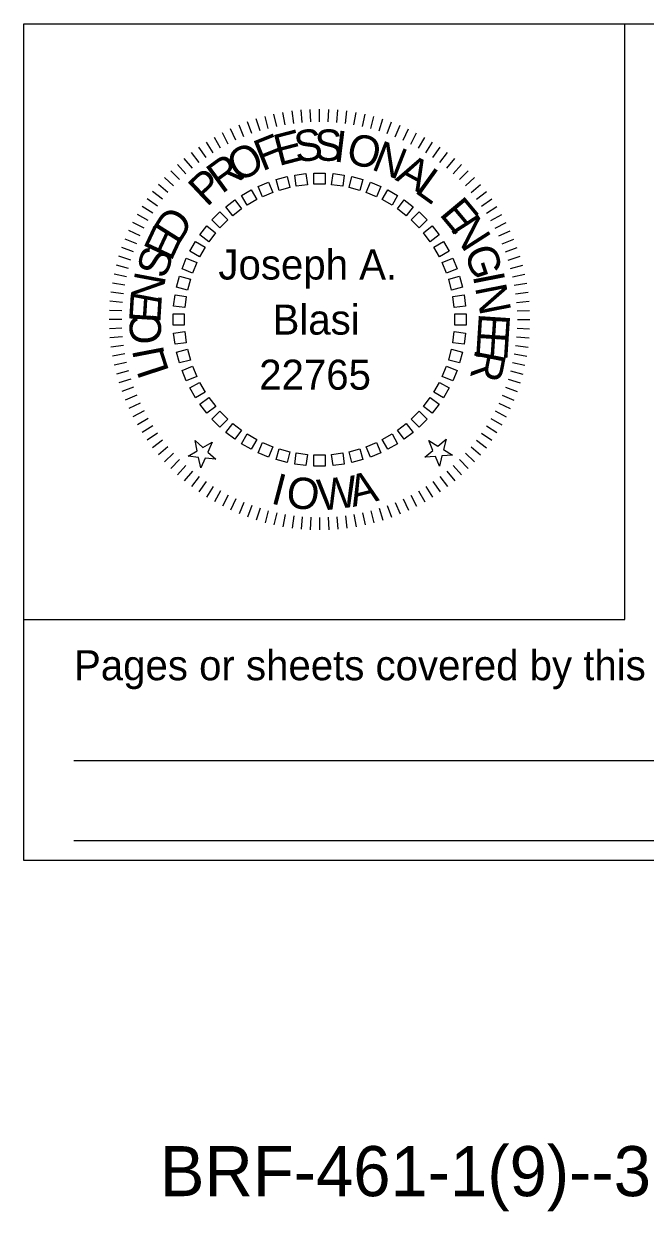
# Model space of a CAD drawing. Extents: x 10040 to 81668, y 7194 to 11018.
# Drawn here: x 12188.1 to 12436.3, y 7193.8 to 7667.9 of the extents above; entities that cross this region are included whole.
import ezdxf

# ---------------------------------------------------------------- set-up
doc = ezdxf.new("R2010")
doc.units = 0
doc.layers.add('dsnCellsSignature', color=7, linetype='Continuous')
doc.layers.add('dsnTextCpn', color=7, linetype='Continuous')

msp = doc.modelspace()

# ---------------------------------------------------------------- linework, layer by layer
at = {"layer": 'dsnCellsSignature'}
for p, q in [((12428.13, 7430.03), (12428.13, 7667.92)), ((12188.13, 7430.03), (12428.13, 7430.03)), ((12208.2, 7373.8), (12918.13, 7373.8)), ((12208.2, 7341.8), (12918.13, 7341.8))]:
    msp.add_line(p, q, dxfattribs=at)
msp.add_lwpolyline([(12188.13, 7667.92), (12938.13, 7667.92), (12938.13, 7333.8), (12188.13, 7333.8)], close=True, dxfattribs=at)
at = {"layer": 'dsnTextCpn'}
for p, q in [((12299.37, 7628.51), (12298.93, 7633.49)), ((12302.8, 7628.73), (12302.58, 7633.73)), ((12306.25, 7628.81), (12306.25, 7633.81)), ((12306.25, 7628.81), (12306.25, 7633.81)), ((12309.7, 7628.73), (12309.91, 7633.73)), ((12313.13, 7628.51), (12313.57, 7633.49)), ((12279.23, 7624.04), (12277.52, 7628.74)), ((12282.49, 7625.15), (12280.99, 7629.92)), ((12285.8, 7626.11), (12284.51, 7630.95)), ((12289.15, 7626.93), (12288.07, 7631.82)), ((12292.53, 7627.61), (12291.66, 7632.53)), ((12295.94, 7628.13), (12295.28, 7633.09)), ((12316.56, 7628.13), (12317.21, 7633.09)), ((12319.97, 7627.61), (12320.84, 7632.53)), ((12323.35, 7626.93), (12324.43, 7631.82)), ((12326.7, 7626.11), (12327.99, 7630.94)), ((12330.01, 7625.15), (12331.51, 7629.92)), ((12333.27, 7624.04), (12334.98, 7628.74)), ((12269.77, 7619.88), (12267.46, 7624.32)), ((12272.86, 7621.4), (12270.75, 7625.94)), ((12276.02, 7622.79), (12274.1, 7627.41)), ((12336.48, 7622.79), (12338.4, 7627.41)), ((12339.64, 7621.4), (12341.75, 7625.94)), ((12342.73, 7619.88), (12345.04, 7624.32)), ((12263.8, 7616.44), (12261.12, 7620.65)), ((12266.75, 7618.22), (12264.25, 7622.55)), ((12345.75, 7618.22), (12348.25, 7622.55)), ((12348.7, 7616.44), (12351.38, 7620.65)), ((12258.15, 7612.48), (12255.11, 7616.45)), ((12260.94, 7614.52), (12258.07, 7618.62)), ((12351.56, 7614.52), (12354.43, 7618.61)), ((12354.34, 7612.48), (12357.39, 7616.45)), ((12252.88, 7608.05), (12249.5, 7611.74)), ((12255.47, 7610.32), (12252.25, 7614.15)), ((12357.03, 7610.32), (12360.25, 7614.15)), ((12359.62, 7608.05), (12363, 7611.74)), ((12248, 7603.18), (12244.32, 7606.56)), ((12250.39, 7605.67), (12246.85, 7609.2)), ((12362.11, 7605.67), (12365.65, 7609.2)), ((12364.5, 7603.18), (12368.18, 7606.56)), ((12243.57, 7597.9), (12239.6, 7600.94)), ((12245.73, 7600.59), (12241.9, 7603.8)), ((12366.77, 7600.59), (12370.6, 7603.8)), ((12368.93, 7597.9), (12372.89, 7600.94)), ((12241.53, 7595.12), (12237.44, 7597.99)), ((12370.97, 7595.12), (12375.06, 7597.99)), ((12237.83, 7589.31), (12233.5, 7591.81)), ((12239.62, 7592.25), (12235.4, 7594.94)), ((12372.88, 7592.25), (12377.1, 7594.94)), ((12374.67, 7589.3), (12379, 7591.8)), ((12236.17, 7586.28), (12231.74, 7588.59)), ((12376.33, 7586.28), (12380.76, 7588.59)), ((12233.26, 7580.04), (12228.64, 7581.95)), ((12234.65, 7583.19), (12230.12, 7585.31)), ((12377.85, 7583.19), (12382.38, 7585.3)), ((12379.24, 7580.04), (12383.86, 7581.95)), ((12232.01, 7576.82), (12227.31, 7578.53)), ((12380.49, 7576.82), (12385.19, 7578.53)), ((12230.9, 7573.56), (12226.13, 7575.06)), ((12381.6, 7573.56), (12386.37, 7575.06)), ((12229.12, 7566.9), (12224.24, 7567.99)), ((12229.94, 7570.25), (12225.11, 7571.55)), ((12382.56, 7570.25), (12387.39, 7571.55)), ((12383.38, 7566.9), (12388.26, 7567.98)), ((12228.45, 7563.52), (12223.52, 7564.39)), ((12384.05, 7563.52), (12388.98, 7564.39)), ((12227.92, 7560.11), (12222.96, 7560.77)), ((12384.58, 7560.11), (12389.53, 7560.77)), ((12227.32, 7553.25), (12222.33, 7553.47)), ((12227.55, 7556.69), (12222.57, 7557.12)), ((12384.95, 7556.69), (12389.93, 7557.12)), ((12385.18, 7553.25), (12390.17, 7553.46)), ((12227.24, 7549.8), (12222.24, 7549.8)), ((12385.25, 7549.8), (12390.25, 7549.8)), ((12227.32, 7546.36), (12222.33, 7546.14)), ((12385.18, 7546.36), (12390.17, 7546.14)), ((12227.55, 7542.92), (12222.57, 7542.48)), ((12227.92, 7539.49), (12222.96, 7538.84)), ((12384.58, 7539.49), (12389.53, 7538.84)), ((12384.95, 7542.92), (12389.93, 7542.48)), ((12228.45, 7536.08), (12223.52, 7535.22)), ((12384.05, 7536.08), (12388.98, 7535.21)), ((12229.12, 7532.7), (12224.24, 7531.62)), ((12229.94, 7529.36), (12225.11, 7528.06)), ((12382.56, 7529.36), (12387.39, 7528.06)), ((12383.38, 7532.7), (12388.26, 7531.62)), ((12230.9, 7526.05), (12226.13, 7524.54)), ((12381.6, 7526.05), (12386.36, 7524.54)), ((12232.01, 7522.78), (12227.31, 7521.07)), ((12380.49, 7522.78), (12385.19, 7521.07)), ((12233.26, 7519.57), (12228.64, 7517.66)), ((12234.65, 7516.42), (12230.12, 7514.3)), ((12377.85, 7516.41), (12382.38, 7514.3)), ((12379.24, 7519.57), (12383.86, 7517.65)), ((12236.17, 7513.32), (12231.74, 7511.01)), ((12237.83, 7510.3), (12233.5, 7507.8)), ((12374.67, 7510.3), (12379, 7507.8)), ((12376.33, 7513.32), (12380.76, 7511.01)), ((12239.62, 7507.36), (12235.4, 7504.67)), ((12372.88, 7507.36), (12377.1, 7504.67)), ((12241.53, 7504.49), (12237.44, 7501.62)), ((12243.57, 7501.71), (12239.6, 7498.66)), ((12368.93, 7501.71), (12372.89, 7498.66)), ((12370.97, 7504.49), (12375.06, 7501.62)), ((12245.73, 7499.02), (12241.9, 7495.81)), ((12248, 7496.43), (12244.31, 7493.05)), ((12364.5, 7496.43), (12368.18, 7493.05)), ((12366.77, 7499.02), (12370.6, 7495.81)), ((12250.38, 7493.94), (12246.85, 7490.4)), ((12252.87, 7491.56), (12249.5, 7487.87)), ((12359.62, 7491.56), (12363, 7487.87)), ((12362.11, 7493.94), (12365.65, 7490.4)), ((12255.47, 7489.28), (12252.25, 7485.45)), ((12258.15, 7487.12), (12255.11, 7483.16)), ((12354.34, 7487.12), (12357.39, 7483.16)), ((12357.03, 7489.28), (12360.25, 7485.45)), ((12260.93, 7485.09), (12258.07, 7480.99)), ((12263.8, 7483.17), (12261.12, 7478.96)), ((12348.7, 7483.17), (12351.38, 7478.95)), ((12351.56, 7485.09), (12354.43, 7480.99)), ((12266.75, 7481.38), (12264.25, 7477.05)), ((12269.77, 7479.72), (12267.46, 7475.29)), ((12272.86, 7478.2), (12270.75, 7473.67)), ((12339.64, 7478.2), (12341.75, 7473.67)), ((12342.73, 7479.72), (12345.04, 7475.29)), ((12345.75, 7481.38), (12348.25, 7477.05)), ((12276.02, 7476.81), (12274.1, 7472.19)), ((12279.23, 7475.56), (12277.52, 7470.87)), ((12282.49, 7474.46), (12280.99, 7469.69)), ((12285.8, 7473.49), (12284.51, 7468.66)), ((12289.15, 7472.67), (12288.07, 7467.79)), ((12323.35, 7472.67), (12324.43, 7467.79)), ((12326.7, 7473.49), (12327.99, 7468.66)), ((12330.01, 7474.46), (12331.51, 7469.69)), ((12333.27, 7475.56), (12334.98, 7470.86)), ((12336.48, 7476.81), (12338.4, 7472.19)), ((12292.53, 7472), (12291.66, 7467.07)), ((12295.94, 7471.48), (12295.28, 7466.52)), ((12299.36, 7471.1), (12298.93, 7466.12)), ((12302.8, 7470.87), (12302.58, 7465.88)), ((12306.25, 7470.8), (12306.25, 7465.8)), ((12309.7, 7470.87), (12309.91, 7465.88)), ((12313.13, 7471.1), (12313.57, 7466.12)), ((12316.56, 7471.47), (12317.21, 7466.52)), ((12319.97, 7472), (12320.84, 7467.07))]:
    msp.add_line(p, q, dxfattribs=at)
for points in [[(12294.45, 7602.55), (12290.1, 7601.38), (12288.93, 7605.73), (12293.28, 7606.9)], [(12301.43, 7603.64), (12296.97, 7603.05), (12296.38, 7607.51), (12300.84, 7608.1)], [(12308.5, 7603.81), (12304, 7603.81), (12304, 7608.31), (12308.5, 7608.31)], [(12315.53, 7603.05), (12311.07, 7603.64), (12311.65, 7608.1), (12316.12, 7607.51)], [(12322.4, 7601.38), (12318.05, 7602.55), (12319.22, 7606.9), (12323.57, 7605.73)], [(12281.2, 7597.7), (12277.3, 7595.45), (12275.05, 7599.34), (12278.95, 7601.59)], [(12287.66, 7600.56), (12283.51, 7598.83), (12281.78, 7602.99), (12285.94, 7604.71)], [(12328.99, 7598.83), (12324.83, 7600.56), (12326.56, 7604.71), (12330.72, 7602.99)], [(12335.2, 7595.45), (12331.3, 7597.7), (12333.55, 7601.59), (12337.45, 7599.34)], [(12275.16, 7594.02), (12271.59, 7591.28), (12268.85, 7594.85), (12272.42, 7597.59)], [(12340.91, 7591.28), (12337.34, 7594.02), (12340.08, 7597.59), (12343.65, 7594.85)], [(12269.65, 7589.58), (12266.47, 7586.4), (12263.29, 7589.58), (12266.47, 7592.76)], [(12346.03, 7586.4), (12342.84, 7589.58), (12346.03, 7592.76), (12349.21, 7589.58)], [(12264.77, 7584.46), (12262.04, 7580.89), (12258.47, 7583.63), (12261.21, 7587.2)], [(12350.46, 7580.89), (12347.72, 7584.46), (12351.29, 7587.2), (12354.03, 7583.63)], [(12260.6, 7578.75), (12258.36, 7574.85), (12254.46, 7577.11), (12256.71, 7581)], [(12354.14, 7574.86), (12351.89, 7578.75), (12355.79, 7581), (12358.04, 7577.11)], [(12257.22, 7572.55), (12255.5, 7568.39), (12251.34, 7570.11), (12253.06, 7574.27)], [(12357, 7568.39), (12355.28, 7572.55), (12359.44, 7574.27), (12361.16, 7570.11)], [(12254.67, 7565.95), (12253.5, 7561.61), (12249.16, 7562.77), (12250.32, 7567.12)], [(12359, 7561.61), (12357.83, 7565.95), (12362.18, 7567.12), (12363.34, 7562.77)], [(12253, 7559.08), (12252.42, 7554.62), (12247.95, 7555.21), (12248.54, 7559.67)], [(12360.08, 7554.62), (12359.5, 7559.08), (12363.96, 7559.67), (12364.55, 7555.21)], [(12252.25, 7552.05), (12252.25, 7547.55), (12247.75, 7547.55), (12247.75, 7552.05)], [(12360.25, 7547.55), (12360.25, 7552.05), (12364.75, 7552.05), (12364.75, 7547.55)], [(12252.41, 7544.98), (12253, 7540.52), (12248.54, 7539.94), (12247.95, 7544.4)], [(12359.5, 7540.52), (12360.08, 7544.99), (12364.55, 7544.4), (12363.96, 7539.94)], [(12253.5, 7538), (12254.67, 7533.65), (12250.32, 7532.49), (12249.16, 7536.83)], [(12357.83, 7533.65), (12358.99, 7538), (12363.34, 7536.83), (12362.18, 7532.49)], [(12255.5, 7531.22), (12257.22, 7527.06), (12253.06, 7525.34), (12251.34, 7529.49)], [(12355.28, 7527.06), (12357, 7531.22), (12361.16, 7529.49), (12359.44, 7525.34)], [(12258.35, 7524.75), (12260.61, 7520.85), (12256.71, 7518.6), (12254.46, 7522.5)], [(12351.89, 7520.85), (12354.14, 7524.75), (12358.04, 7522.5), (12355.79, 7518.6)], [(12262.04, 7518.71), (12264.78, 7515.14), (12261.21, 7512.4), (12258.47, 7515.97)], [(12347.72, 7515.14), (12350.46, 7518.71), (12354.03, 7515.97), (12351.29, 7512.4)], [(12266.47, 7513.21), (12269.65, 7510.03), (12266.47, 7506.84), (12263.29, 7510.03)], [(12342.84, 7510.03), (12346.03, 7513.21), (12349.21, 7510.03), (12346.03, 7506.85)], [(12271.59, 7508.33), (12275.16, 7505.59), (12272.42, 7502.02), (12268.85, 7504.76)], [(12337.34, 7505.59), (12340.91, 7508.33), (12343.65, 7504.76), (12340.08, 7502.02)], [(12256.53, 7501.53), (12259.68, 7498.68), (12263.37, 7500.81), (12261.64, 7496.92), (12264.8, 7494.07), (12260.57, 7494.52), (12258.84, 7490.63), (12257.96, 7494.8), (12253.73, 7495.24), (12257.41, 7497.37)], [(12277.3, 7504.16), (12281.2, 7501.91), (12278.95, 7498.01), (12275.05, 7500.26)], [(12283.51, 7500.77), (12287.66, 7499.05), (12285.94, 7494.89), (12281.78, 7496.61)], [(12324.84, 7499.05), (12328.99, 7500.77), (12330.72, 7496.61), (12326.56, 7494.89)], [(12331.3, 7501.91), (12335.2, 7504.16), (12337.45, 7500.26), (12333.55, 7498.01)], [(12349.95, 7501.55), (12353.56, 7499.29), (12356.82, 7502.03), (12355.79, 7497.9), (12359.4, 7495.64), (12355.15, 7495.35), (12354.12, 7491.22), (12352.53, 7495.17), (12348.28, 7494.87), (12351.55, 7497.6)], [(12290.1, 7498.22), (12294.45, 7497.06), (12293.28, 7492.71), (12288.93, 7493.88)], [(12296.97, 7496.56), (12301.43, 7495.97), (12300.84, 7491.51), (12296.38, 7492.09)], [(12311.07, 7495.97), (12315.53, 7496.56), (12316.12, 7492.09), (12311.65, 7491.51)], [(12318.05, 7497.06), (12322.4, 7498.22), (12323.57, 7493.88), (12319.22, 7492.71)], [(12304, 7495.8), (12308.5, 7495.8), (12308.5, 7491.3), (12304, 7491.3)]]:
    msp.add_lwpolyline(points, close=True, dxfattribs=at)

# ---------------------------------------------------------------- texts
at = {"layer": 'dsnCellsSignature'}
msp.add_text('L', height=12.5, rotation=324.2434, dxfattribs=at).set_placement((12343.78, 7600.88))
msp.add_text('Pages or sheets covered by this seal:', height=12, dxfattribs=at).set_placement((12208.2, 7405.8))
at = {"layer": 'dsnTextCpn'}
for s, rotation, p in [('F', 21.7736, (12283.38, 7608.92)), ('E', 14.5823, (12289.94, 7611.05)), ('S', 7.3911, (12296.96, 7612.51)), ('S', 0.1998, (12304.26, 7613.18)), ('I', 353.0085, (12311.59, 7613)), ('O', 345.8172, (12316.32, 7612.63)), ('O', 28.9649, (12273.86, 7604.32)), ('N', 338.6259, (12326.56, 7609.91)), ('R', 36.1562, (12267.22, 7599.78)), ('A', 331.4346, (12336.18, 7605.67)), ('P', 43.3475, (12261.26, 7594.5)), ('E', 309.8608, (12353.77, 7591.78)), ('D', 57.7301, (12249.9, 7579.28)), ('N', 302.6695, (12358.22, 7586.16)), ('E', 64.9213, (12246.99, 7572.7)), ('S', 72.1126, (12244.78, 7565.69)), ('G', 288.2869, (12363.93, 7577.23)), ('N', 79.3039, (12242.8, 7555.35)), ('I', 281.0956, (12367.39, 7567.38)), ('N', 281.0956, (12368.3, 7562.74)), ('E', 86.4952, (12242.65, 7548.14)), ('C', 93.6865, (12243.35, 7540.25)), ('E', 266.2773, (12369.94, 7552.57)), ('E', 266.2773, (12369.48, 7545.4)), ('I', 100.8778, (12244.43, 7535.63)), ('L', 108.069, (12246.33, 7529.14)), ('R', 259.086, (12368.58, 7538.29)), ('I', 345.2906, (12286.37, 7476.57)), ('O', 352.4819, (12292.48, 7475.08)), ('W', 6.8645, (12306.18, 7473.37)), ('A', 14.0557, (12319.59, 7474.92))]:
    msp.add_text(s, height=12.5, rotation=rotation, dxfattribs=at).set_placement(p)
for s, height, p in [('Joseph A. ', 12.001, (12265.88, 7565.8)), ('Blasi', 12.001, (12287.5, 7543.8)), ('22765', 12.001, (12282.16, 7521.8)), ('BRF-461-1(9)--38-82', 20, (12242.46, 7199.81))]:
    msp.add_text(s, height=height, dxfattribs=at).set_placement(p)

doc.saveas('drawing.dxf')
